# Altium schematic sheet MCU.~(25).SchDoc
size A3; SheetNumber: 10; SheetTotal: 10
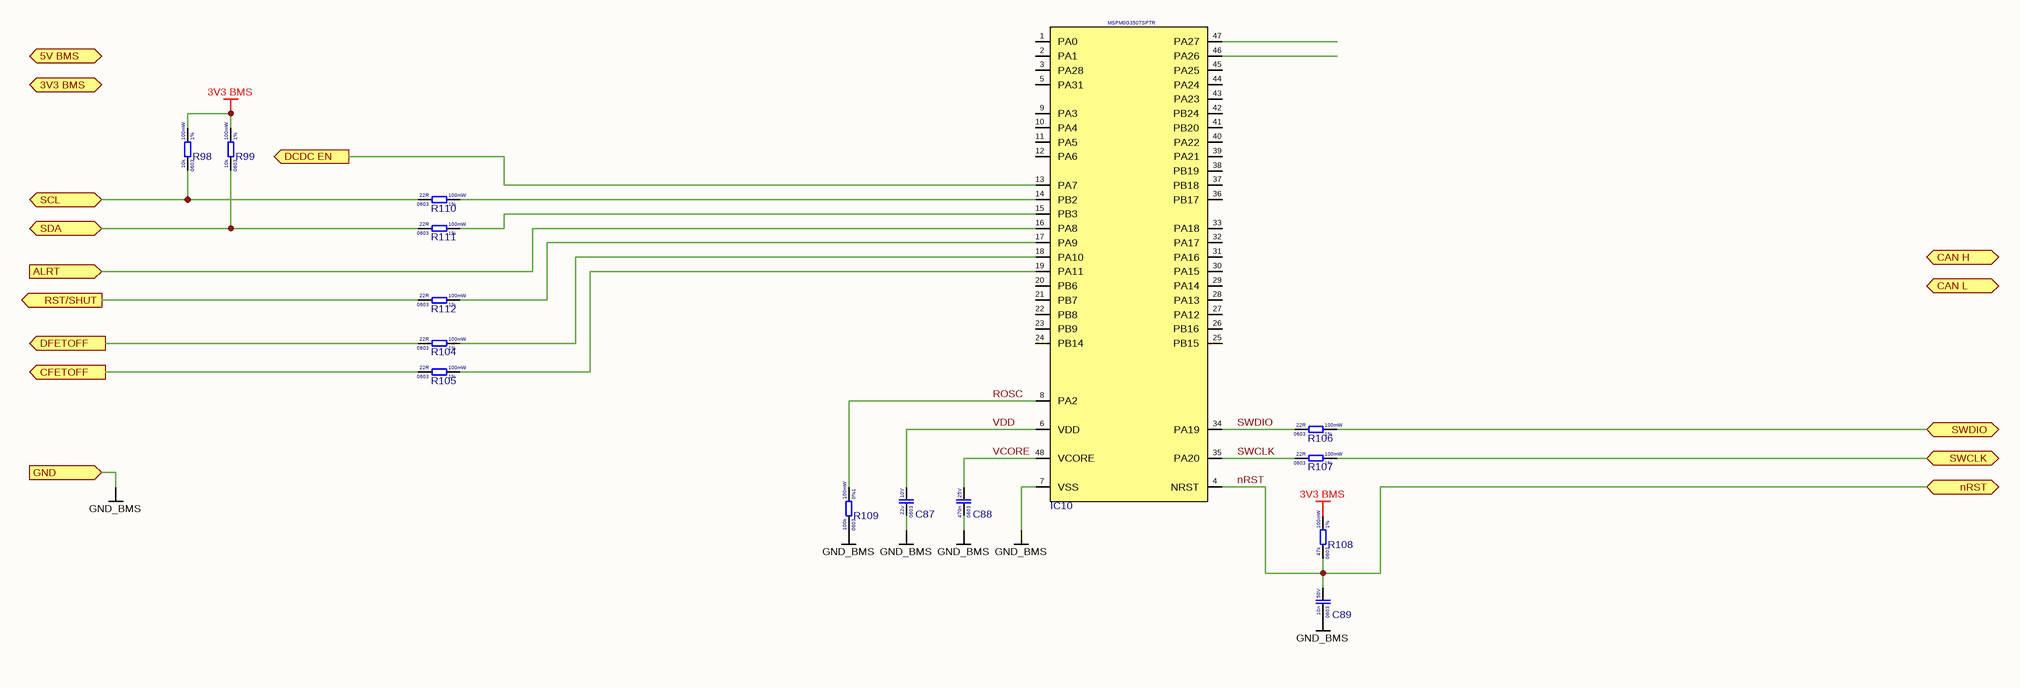
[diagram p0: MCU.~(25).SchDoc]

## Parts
C87  Voltage Rating: 10V  Case Code (Imperial): 0603  Capacitance: 22u  [CAP 0603]  (hidden comment: CGA0603X5R226M100JT)
C88  Voltage Rating: 25V  Case Code (Imperial): 0603  Capacitance: 470n  [CAP 0603]  (hidden comment: CL10B474KA8NNNC)
C89  Voltage Rating: 50V  Case Code (Imperial): 0603  Capacitance: 10n  [CAP 0603]  (hidden comment: 0603B103K500NT)
IC10  MSPM0G3507SPTR  [LQFP-48]
R98  Resistance Tolerance: 1%  Resistance: 10k  Power Rating: 100mW  Case Code (Imperial): 0603  [RES_0603]  (hidden comment: 0603WAF1002T5E)
R99  Resistance Tolerance: 1%  Resistance: 10k  Power Rating: 100mW  Case Code (Imperial): 0603  [RES_0603]  (hidden comment: 0603WAF1002T5E)
R104  Resistance Tolerance: 1%  Resistance: 22R  Power Rating: 100mW  Case Code (Imperial): 0603  [RES_0603]  (hidden comment: 0603WAF220JT5E)
R105  Resistance Tolerance: 1%  Resistance: 22R  Power Rating: 100mW  Case Code (Imperial): 0603  [RES_0603]  (hidden comment: 0603WAF220JT5E)
R106  Resistance Tolerance: 1%  Resistance: 22R  Power Rating: 100mW  Case Code (Imperial): 0603  [RES_0603]  (hidden comment: 0603WAF220JT5E)
R107  Resistance Tolerance: 1%  Resistance: 22R  Power Rating: 100mW  Case Code (Imperial): 0603  [RES_0603]  (hidden comment: 0603WAF220JT5E)
R108  Resistance Tolerance: 1%  Resistance: 47k  Power Rating: 100mW  Case Code (Imperial): 0603  [RES_0603]  (hidden comment: 0603WAF4702T5E)
R109  Resistance Tolerance: 0%1  Resistance: 100k  Power Rating: 100mW  Case Code (Imperial): 0603  [RES_0603]  (hidden comment: RT0603BRD07100KL)
R110  Resistance Tolerance: 1%  Resistance: 22R  Power Rating: 100mW  Case Code (Imperial): 0603  [RES_0603]  (hidden comment: 0603WAF220JT5E)
R111  Resistance Tolerance: 1%  Resistance: 22R  Power Rating: 100mW  Case Code (Imperial): 0603  [RES_0603]  (hidden comment: 0603WAF220JT5E)
R112  Resistance Tolerance: 1%  Resistance: 22R  Power Rating: 100mW  Case Code (Imperial): 0603  [RES_0603]  (hidden comment: 0603WAF220JT5E)

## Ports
3V3 BMS (bidir, see BMS[4B]), 5V BMS (bidir, see BMS[4B]), ALRT (in, see BMS[4B], BQ76952 BMS[7C]), CAN H (bidir, see BMS[4B], BMS[8B]), CAN L (bidir, see BMS[4B], BMS[8B]), CFETOFF (out, see BMS[4B], BQ76952 BMS[7C]), DCDC EN (out, see BMS[4B]), DFETOFF (out, see BMS[4B], BQ76952 BMS[7C]), GND (in, see BMS[4C], BQ76952 BMS[1D]), nRST (bidir, see BMS[4B], BMS[8B]), RST/SHUT (out, see BMS[4B], BQ76952 BMS[7C]), SCL (bidir, see BMS[4C], BMS[8C], BQ76952 BMS[7C]), SDA (bidir, see BMS[4C], BMS[8C], BQ76952 BMS[7C]), SWCLK (bidir, see BMS[4B], BMS[8B]), SWDIO (bidir, see BMS[4B], BMS[8B])

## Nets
3V3 BMS: R98.2 R99.2 R108.2
GND_BMS: C87.1 C88.1 C89.1 IC10.7(VSS) R109.1 ; port GND
ALRT: IC10.16(PA8) ; port ALRT
CFETOFF: R105.1 ; port CFETOFF
DCDC EN: IC10.13(PA7) ; port DCDC EN
DFETOFF: R104.1 ; port DFETOFF
nRST: C89.2 IC10.4(NRST) R108.1 ; port nRST
ROSC: IC10.8(PA2) R109.2
RST/SHUT: R112.1 ; port RST/SHUT
SCL: R98.1 R110.1 ; port SCL
SDA: R99.1 R111.1 ; port SDA
SWCLK: IC10.35(PA20) R107.1
SWCLK: R107.2 ; port SWCLK  [a separate net that carries the same name]
SWDIO: IC10.34(PA19) R106.1
SWDIO: R106.2 ; port SWDIO  [a separate net that carries the same name]
VCORE: C88.2 IC10.48(VCORE)
VDD: C87.2 IC10.6(VDD)
NetIC10_14: IC10.14(PB2) R110.2
NetIC10_15: IC10.15(PB3) R111.2
NetIC10_17: IC10.17(PA9) R112.2
NetIC10_18: IC10.18(PA10) R104.2
NetIC10_19: IC10.19(PA11) R105.2

Not connected (* = marked no-connect by the designer): IC10 1(PA0) 2(PA1) 3(PA28) 5(PA31) 9(PA3) 10(PA4) 11(PA5) 12(PA6) 20(PB6) 21(PB7) 22(PB8) 23(PB9) 24(PB14) 25(PB15) 26(PB16) 27(PA12) 28(PA13) 29(PA14) 30(PA15) 31(PA16) 32(PA17) 33(PA18) 36(PB17) 37(PB18) 38(PB19) 39(PA21) 40(PA22) 41(PB20) 42(PB24) 43(PA23) 44(PA24) 45(PA25) 46(PA26) 47(PA27)

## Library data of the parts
C87 = CGA0603X5R226M100JT: Cap 22uF 10V 0603 X5R; Manufacturer: HRE
C88 = CL10B474KA8NNNC: Cap 470nF 25V 0603 X7R; Manufacturer: Samsung
C89 = 0603B103K500NT: Cap 10nF 50V 0603 X7R; Manufacturer: FH
IC10 = MSPM0G3507SPTR: MCU MSPM0G3507SPTR LQFP-48; Manufacturer: Texas Instruments
R98 R99 = 0603WAF1002T5E: Res 10k 0603 1% 100mW 75V; Manufacturer: Uni-Royal
R104-R107 R110-R112 = 0603WAF220JT5E: Res 22R 0603 1% 100mW 75V; Manufacturer: Uni-Royal
R108 = 0603WAF4702T5E: Res 47k 0603 1% 100mW 75V; Manufacturer: Uni-Royal
R109 = RT0603BRD07100KL: Res 100k 0603 0.1% 100mW 75V 25ppm; Manufacturer: YAGEO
